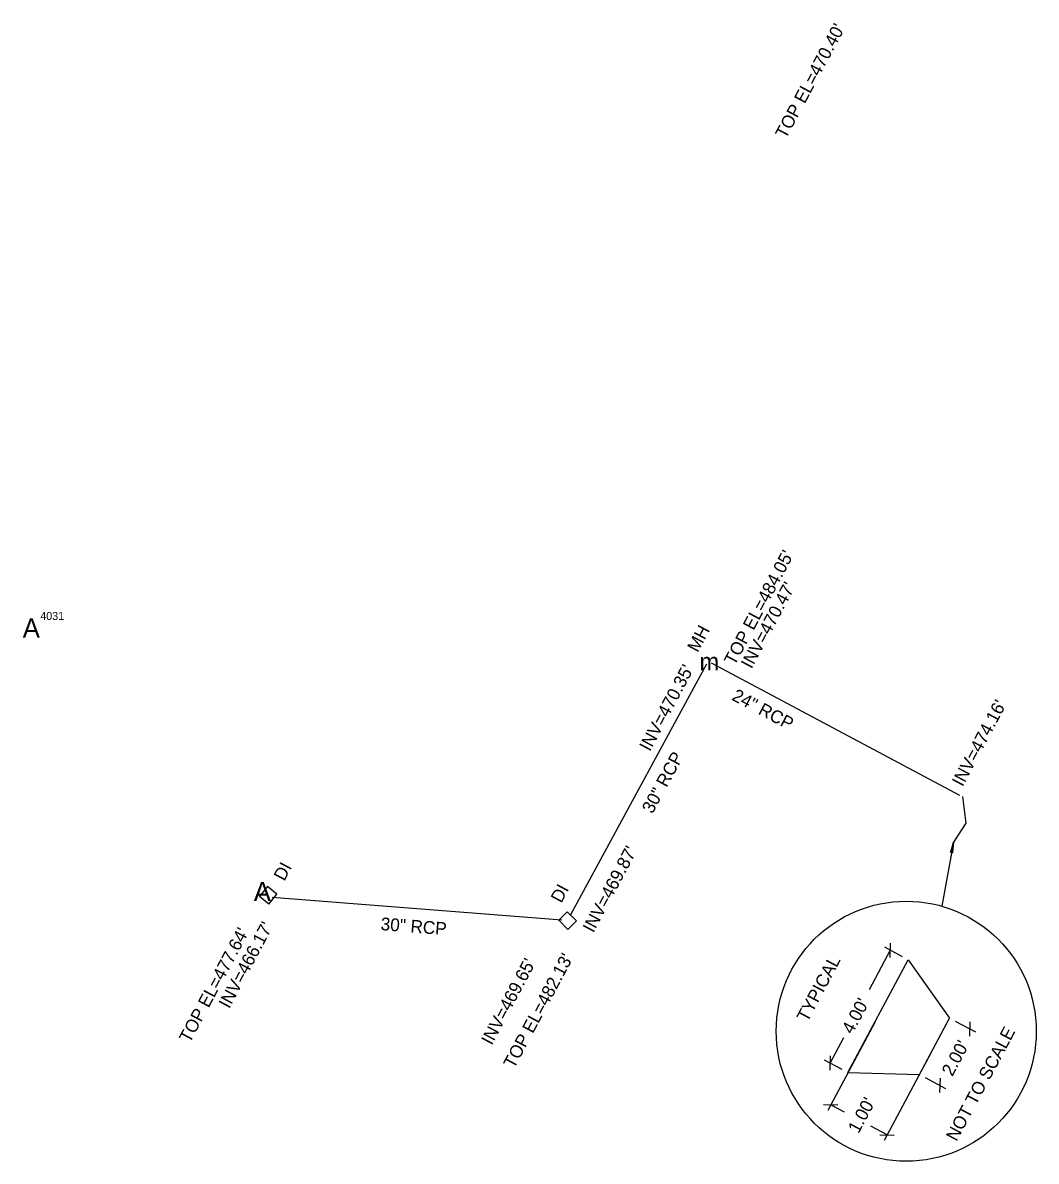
# Model space of a CAD drawing. Extents: x 1975859 to 1978323, y 778892 to 782836.
# Drawn here: x 1975859.5 to 1976176.1, y 778891.6 to 779247.3 of the extents above; entities that cross this region are included whole.
import ezdxf

# ---------------------------------------------------------------- set-up
doc = ezdxf.new("R2010")
doc.units = 0
for name, color, linetype in [('Exist Structure Minor Catch Basin Top Elevation', 7, 'Continuous'), ('Exist Structure Minor Drop Inlet', 7, 'Continuous'), ('Exist Structure Minor Drop Inlet Text', 7, 'Continuous'), ('Exist Structure Minor Drop Inlet Top Elevation', 7, 'Continuous'), ('Exist Structure Minor Pipes RCP 24 Inch', 7, 'Continuous'), ('Exist Structure Minor Pipes RCP 24 Inch Invert', 7, 'Continuous'), ('Exist Structure Minor Pipes RCP 24 Inch Text', 7, 'Continuous'), ('Exist Structure Minor Pipes RCP 30 Inch', 7, 'Continuous'), ('Exist Structure Minor Pipes RCP 30 Inch Invert', 7, 'Continuous'), ('Exist Structure Minor Pipes RCP 30 Inch Text', 7, 'Continuous'), ('Exist Structure Minor Pipes RCP 36 Inch Cogo Number', 7, 'Continuous'), ('Exist Structure Minor Pipes RCP 36 Inch Cogo Point CELL', 7, 'Continuous'), ('Exist Structure Minor Storm Sewer Manhole CELL', 7, 'Continuous'), ('Exist Structure Minor Storm Sewer Manhole Text', 7, 'Continuous'), ('Exist Structure Minor Storm Sewer Manhole Top Elevation', 7, 'Continuous'), ('Scratch_Level_8', 7, 'Continuous')]:
    doc.layers.add(name, color=color, linetype=linetype)

msp = doc.modelspace()

# ---------------------------------------------------------------- linework, layer by layer
at = {"layer": 'Exist Structure Minor Drop Inlet'}
for p, q in [((1975936.34, 778971.87), (1975933.42, 778974.27)), ((1975936.34, 778971.87), (1975938.91, 778975.01)), ((1976026.93, 778966.83), (1976029.58, 778969.53))]:
    msp.add_line(p, q, dxfattribs=at)
for points in [[(1975938.91, 778975.01), (1975935.99, 778977.4), (1975933.41, 778974.26)], [(1976029.58, 778969.53), (1976032.47, 778966.69), (1976029.81, 778963.98), (1976026.93, 778966.83)]]:
    msp.add_lwpolyline(points, dxfattribs=at)
at = {"layer": 'Exist Structure Minor Pipes RCP 24 Inch'}
msp.add_line((1976074.62, 779047.26), (1976152.22, 779005.91), dxfattribs=at)
at = {"layer": 'Exist Structure Minor Pipes RCP 30 Inch'}
for p, q in [((1976073.17, 779046.82), (1976030.64, 778968.51)), ((1976027.94, 778966.86), (1975937.4, 778973.97))]:
    msp.add_line(p, q, dxfattribs=at)
at = {"layer": 'Scratch_Level_8'}
for p, q in [((1976150.29, 778991.22), (1976146.7, 778971.23)), ((1976149.97, 778987.91), (1976149.44, 778988)), ((1976149.5, 778988.04), (1976149.76, 778988.27)), ((1976149.76, 778988.27), (1976149.56, 778987.98)), ((1976149.76, 778988.27), (1976149.65, 778987.96)), ((1976149.76, 778988.27), (1976149.93, 778987.96)), ((1976149.76, 778988.27), (1976149.87, 778987.92)), ((1976149.76, 778988.27), (1976149.76, 778987.94)), ((1976134.36, 778955.47), (1976128.8, 778958.44)), ((1976130.5, 778955.26), (1976130.62, 778959.73)), ((1976117.29, 778919.24), (1976136.13, 778954.53)), ((1976130.56, 778957.5), (1976123.93, 778945.08)), ((1976136.13, 778954.53), (1976149.06, 778936.29)), ((1976125.77, 778935.12), (1976110.98, 778907.41)), ((1976139.65, 778918.65), (1976149.06, 778936.29)), ((1976150.83, 778935.35), (1976157.2, 778931.95)), ((1976155.38, 778930.65), (1976155.49, 778935.13)), ((1976111.73, 778922.21), (1976115.99, 778930.2)), ((1976115.53, 778920.18), (1976109.97, 778923.15)), ((1976111.79, 778924.44), (1976111.67, 778919.97)), ((1976143.41, 778925.7), (1976128.63, 778897.99)), ((1976117.29, 778919.24), (1976139.65, 778918.65)), ((1976141.41, 778917.7), (1976147.78, 778914.3)), ((1976146.08, 778917.48), (1976145.96, 778913.01)), ((1976114.16, 778909.11), (1976109.69, 778909.23)), ((1976111.92, 778909.17), (1976116.09, 778906.95)), ((1976129.57, 778899.76), (1976124.43, 778902.5)), ((1976127.33, 778899.82), (1976131.8, 778899.7))]:
    msp.add_line(p, q, dxfattribs=at)
for points in [[(1976153.06, 779005.55), (1976154.15, 778997.14), (1976150.29, 778991.22)], [(1976149.97, 778987.91), (1976150.1, 778988.12), (1976150.29, 778991.22), (1976149.39, 778988.24), (1976149.44, 778988)], [(1976149.42, 778988.12), (1976150.29, 778991.22), (1976150.03, 778988.01)], [(1976149.94, 778988.07), (1976150.29, 778991.22), (1976149.97, 778987.91), (1976149.93, 778987.96), (1976149.94, 778988.07), (1976149.76, 778988.27), (1976149.53, 778988.14), (1976149.5, 778988.04), (1976149.44, 778988), (1976150.29, 778991.22), (1976149.53, 778988.14)], [(1976150.25, 778991.05), (1976150.28, 778991.12), (1976150.27, 778991.03), (1976150.26, 778990.94), (1976150.26, 778991.03), (1976150.23, 778990.96), (1976150.21, 778990.87), (1976150.24, 778990.94), (1976150.25, 778990.84), (1976150.24, 778990.75), (1976150.23, 778990.85), (1976150.18, 778990.78), (1976150.16, 778990.69), (1976150.21, 778990.76), (1976150.23, 778990.66), (1976150.22, 778990.57), (1976150.19, 778990.66), (1976150.14, 778990.59), (1976150.12, 778990.5), (1976150.18, 778990.57), (1976150.21, 778990.47), (1976150.2, 778990.38), (1976150.16, 778990.48), (1976150.09, 778990.41), (1976150.07, 778990.32), (1976150.14, 778990.39), (1976150.19, 778990.29), (1976150.18, 778990.19), (1976150.13, 778990.3), (1976150.05, 778990.23), (1976150.02, 778990.14), (1976150.11, 778990.2), (1976150.17, 778990.1), (1976150.16, 778990.01), (1976150.09, 778990.11), (1976150, 778990.05), (1976149.98, 778989.96), (1976150.08, 778990.02), (1976150.15, 778989.92), (1976150.13, 778989.82), (1976150.06, 778989.93), (1976149.96, 778989.87), (1976149.93, 778989.78), (1976150.04, 778989.84), (1976150.12, 778989.73), (1976150.11, 778989.64), (1976150.03, 778989.74), (1976149.91, 778989.69), (1976149.89, 778989.6), (1976150.01, 778989.65), (1976150.1, 778989.54), (1976150.09, 778989.45), (1976149.99, 778989.56), (1976149.87, 778989.5), (1976149.84, 778989.41), (1976149.98, 778989.47), (1976150.08, 778989.36), (1976150.07, 778989.26), (1976149.96, 778989.37), (1976149.82, 778989.32), (1976149.8, 778989.23), (1976149.95, 778989.28), (1976150.06, 778989.17), (1976150.05, 778989.08), (1976149.93, 778989.19), (1976149.78, 778989.14), (1976149.75, 778989.05), (1976149.91, 778989.1), (1976150.04, 778988.98), (1976150.03, 778988.89), (1976149.9, 778989), (1976149.73, 778988.96), (1976149.71, 778988.87), (1976149.88, 778988.91), (1976150.02, 778988.8), (1976150.01, 778988.71), (1976149.86, 778988.82), (1976149.68, 778988.78), (1976149.66, 778988.69), (1976149.85, 778988.73), (1976150, 778988.61), (1976149.99, 778988.52), (1976149.83, 778988.64), (1976149.64, 778988.6), (1976149.62, 778988.51), (1976149.81, 778988.54), (1976149.98, 778988.43), (1976149.97, 778988.33), (1976149.8, 778988.45), (1976149.59, 778988.41), (1976149.57, 778988.32), (1976149.78, 778988.36), (1976149.96, 778988.24), (1976149.95, 778988.15), (1976149.76, 778988.27), (1976149.55, 778988.23)]]:
    msp.add_lwpolyline(points, dxfattribs=at)
msp.add_circle((1976135.53, 778932.18), 40.62, dxfattribs=at)

# ---------------------------------------------------------------- texts
at = {"layer": 'Exist Structure Minor Catch Basin Top Elevation'}
msp.add_text("TOP EL=470.40'", height=4, rotation=61.9141, dxfattribs=at).set_placement((1976097.93, 779210.76))
at = {"layer": 'Exist Structure Minor Drop Inlet Text'}
for p in [(1975941.19, 778978.86), (1976027.76, 778971.99)]:
    msp.add_text('DI', height=4, rotation=61.9141, dxfattribs=at).set_placement(p)
at = {"layer": 'Exist Structure Minor Drop Inlet Top Elevation'}
for s, p in [("TOP EL=477.64'", (1975911.66, 778928.25)), ("TOP EL=482.13'", (1976012.98, 778920.24))]:
    msp.add_text(s, height=4, rotation=61.9141, dxfattribs=at).set_placement(p)
at = {"layer": 'Exist Structure Minor Pipes RCP 24 Inch Invert'}
for s, p in [("INV=470.47'", (1976087.19, 779045.19)), ("INV=474.16'", (1976153.12, 779008.36))]:
    msp.add_text(s, height=4, rotation=61.9141, dxfattribs=at).set_placement(p)
at = {"layer": 'Exist Structure Minor Pipes RCP 24 Inch Text'}
msp.add_text('24" RCP', height=4, rotation=331.9487, dxfattribs=at).set_placement((1976080.75, 779035.83))
at = {"layer": 'Exist Structure Minor Pipes RCP 30 Inch Invert'}
for s, p in [("INV=470.35'", (1976055.43, 779019.37)), ("INV=469.87'", (1976037.74, 778962.7)), ("INV=466.17'", (1975923.98, 778939.02)), ("INV=469.65'", (1976006.01, 778927.59))]:
    msp.add_text(s, height=4, rotation=61.9141, dxfattribs=at).set_placement(p)
at = {"layer": 'Exist Structure Minor Pipes RCP 30 Inch Text'}
for rotation, p in [(61.4966, (1976056.23, 778999.92)), (355.5103, (1975971.2, 778963.79))]:
    msp.add_text('30" RCP', height=4, rotation=rotation, dxfattribs=at).set_placement(p)
at = {"layer": 'Exist Structure Minor Pipes RCP 36 Inch Cogo Number'}
msp.add_text('4031', height=2.5, dxfattribs=at).set_placement((1975864.96, 779060.68))
at = {"layer": 'Exist Structure Minor Pipes RCP 36 Inch Cogo Point CELL'}
for p in [(1975859.46, 779055.18), (1975931.67, 778972.82)]:
    msp.add_text('A', height=6, dxfattribs=at).set_placement(p)
at = {"layer": 'Exist Structure Minor Storm Sewer Manhole CELL'}
msp.add_text('m', height=5.5, dxfattribs=at).set_placement((1976070.93, 779044.91))
at = {"layer": 'Exist Structure Minor Storm Sewer Manhole Text'}
msp.add_text('MH', height=4, rotation=61.9141, dxfattribs=at).set_placement((1976070.42, 779050.29))
at = {"layer": 'Exist Structure Minor Storm Sewer Manhole Top Elevation'}
msp.add_text("TOP EL=484.05'", height=4, rotation=61.9141, dxfattribs=at).set_placement((1976081.93, 779046.2))
at = {"layer": 'Scratch_Level_8'}
for s, p in [('TYPICAL', (1976104.65, 778934.8)), ("4.00'", (1976118.7, 778931.02)), ('NOT TO SCALE', (1976151.26, 778897.52)), ("2.00'", (1976149.92, 778917.83)), ("1.00'", (1976120.63, 778900))]:
    msp.add_text(s, height=4, rotation=61.9141, dxfattribs=at).set_placement(p)

doc.saveas('drawing.dxf')
